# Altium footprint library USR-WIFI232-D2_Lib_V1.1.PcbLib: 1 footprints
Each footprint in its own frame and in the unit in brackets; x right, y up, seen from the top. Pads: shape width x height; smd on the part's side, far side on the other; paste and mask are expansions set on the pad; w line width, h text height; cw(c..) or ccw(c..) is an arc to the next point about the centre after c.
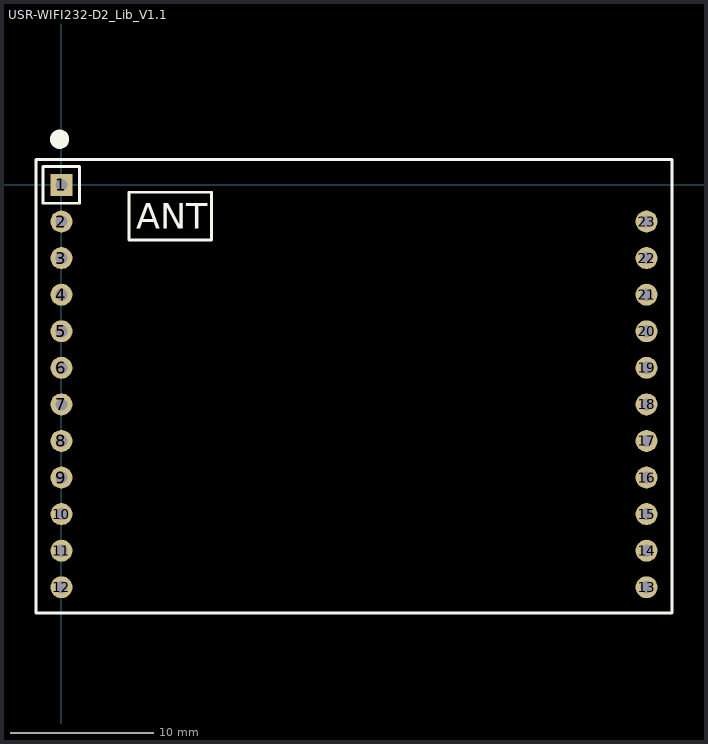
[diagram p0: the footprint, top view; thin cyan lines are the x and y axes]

## USR-WIFI232-D2_Lib_V1.1 [mil]
pads (23):
  rect 60x60 hole 33.47: 1(0,0)
  round 60 hole 33.47: 2(0,-100) 3(0,-200) 4(0,-300) 5(0,-400) 6(0,-500) 7(0,-600) 8(0,-700) 9(0,-800) 10(0,-900) 11(0,-1000) 12(0,-1100) 13(1600,-1100) 14(1600,-1000) 15(1600,-900) 16(1600,-800) 17(1600,-700) 18(1600,-600) 19(1600,-500) 20(1600,-400) 21(1600,-300) 22(1600,-200) 23(1600,-100)
Top Overlay:
  circle w30: c-5,125 r11.18
  lines w8: -70,-1170 1670,-1170 1670,70 -70,70 -70,-1170 ; -50,-50 50,-50 50,50 -50,50 -50,-50 ; 185,-150 410,-150 410,-20 185,-20 185,-150
  text "ANT" at 205,-120 h70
